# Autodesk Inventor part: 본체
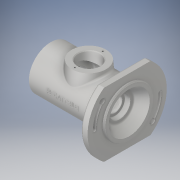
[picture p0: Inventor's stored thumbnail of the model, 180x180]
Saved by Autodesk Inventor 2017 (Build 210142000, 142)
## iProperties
Part Number: 본체
Material: 알루미늄 6061
Document SubType Name: Modeling
Designer: Administrator
Density: 2.7 g/cm^3
Appearance: 알루미늄 - 평지
Mass: 687.877 g
Surface Area: 621.651 cm^2
Volume: 254.769 cm^3
Author: Administrator
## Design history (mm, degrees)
sketch "스케치1"
  geometry: L1 (0, 0)-(102, 0); L2 (0, 0)-(0, 32); L3 (0, 32)-(102, 32); L4 (102, 32)-(102, 0)
  constraints: 8 end point, 2 horizontal, 1 perpendicular, 1 vertical
  dimensions: "d0" = 102 distance of L1.start L1.end; "d1" = 64 diameter of L3 L1
revolve "회전1" sketch "스케치1" stored, may be unused: angle "d2" = 90 deg
sketch "스케치2"
  geometry: L1 (-33.985, 47)-(33.985, 47); L2 (-33.985, -47)-(33.985, -47); A1 r 58 centre (0, 0) between (-33.985, 47) and (-33.985, -47); A2 r 58 centre (0, 0) between (33.985, 47) and (-33.985, 47); A3 r 58 centre (0, 0) between (33.985, -47) and (33.985, 47); A4 r 58 centre (0, 0) between (-33.985, -47) and (33.985, -47); 1 further point
  constraints: 9 point on circle, 4 centre point, 4 end point, 2 horizontal, 1 coincident
  dimensions: "d3" = 116 diameter of A1; "d4" = 94 distance between parallel lines of L2 L1; "d5" = 47 distance from line of point (0, 0) L1
extrude "돌출1" join sketch "스케치2" distance "d6" = 10; taper "d7" = 0 deg
sketch "스케치3"
  geometry: C1 r 36 at (0, 0); 1 further point
  constraints: 1 centre point, 1 coincident
  dimensions: "d8" = 72 diameter of C1
extrude "돌출2" join sketch "스케치3" distance "d9" = 3; taper "d10" = 0 deg
sketch "스케치4"
  geometry: L1 (115, 0)-(8, 0); L2 (8, 0)-(8, 24); L3 (0, -32)-(0, 32) reference; L4 (8, 24)-(11, 24); L5 (11, 24)-(11, 22.5); L6 (11, 22.5)-(22, 22.5); L7 (22, 22.5)-(22, 17.5); L8 (22, 17.5)-(24.25, 17.5); L9 (24.25, 17.5)-(24.25, 18.5); L10 (24.25, 18.5)-(26, 18.5); L11 (26, 18.5)-(26, 17.5); L12 (26, 17.5)-(37, 17.5); L13 (37, 17.5)-(37, 27); L14 (37, 27)-(75, 27); L15 (75, 27)-(75, 17.5); L16 (75, 17.5)-(85.4, 17.5); L17 (86, 16.9)-(86, 15); L18 (86, 15)-(91, 15); L19 (91, 15)-(91, 11); L20 (91, 11)-(93.7, 11); L21 (93.7, 11)-(93.7, 14.5); L22 (101, 15.404)-(101, 20); L23 (101, 20)-(115, 30); L24 (115, -36)-(115, 36) reference; L25 (94.2, 15)-(100.3, 15); L26 (100.3, 15)-(101, 15.404); L27 (115, 30)-(115, 0); A1 r 0.5 centre (94.2, 14.5) between (94.2, 15) and (93.7, 14.5); A2 r 0.6 centre (85.4, 16.9) between (86, 16.9) and (85.4, 17.5); 4 further points
  constraints: 50 end point, 10 perpendicular, 6 horizontal, 5 point on line, 4 point on circle, 4 tangent, 4 vertical, 3 midpoint, 2 centre point, 2 collinear, 2 horizontal alignment
  dimensions: "d11" = 8 distance between parallel lines of L3 L2; "d12" = 48 diameter of L4 L1; "d13" = 3 distance of L2.end L4.end; "d14" = 45 diameter of L6 L1; "d15" = 37 diameter of L10 L1; "d16" = 4 distance between parallel lines of L11 L7; "d17" = 1.75 distance of L9.end L10.end; "d19" = 35 diameter of L12 L1; "d20" = 22 distance between parallel lines of L3 L7; "d21" = 11 horizontal distance of L13.end L10.end; "d22" = 38 distance of L13.end L14.end; "d23" = 54 diameter of L14 L1; "d24" = 30 diameter of L18 L1; "d25" = 22 diameter of L20 L1; "d27" = 40 diameter of L22.end L1; "d28" = 11 distance of L15.end point (86, 17.5); "d29" = 5 distance of L17.end L18.end; "d30" = 14 distance between parallel lines of L22 L24; "d31" = 7.3 distance between parallel lines of L22 L21; "d32" = 30 diameter of L25 L1; "d33" = 0.7 distance from line of L22 L25.end; "d34" = 30 deg angle of L25 L26; "d35" = 0.5 radius of A1 (derived); "d36" = 0.6 radius of A2; "d37" = 60 diameter of L23.end L1
revolve "회전2" sketch "스케치4" stored, may be unused: angle "d38" = 90 deg
node "작업 평면1"
sketch "스케치5"
  geometry: L1 (0, 32)-(0, -32) reference; C1 r 25 at (-56, 0); 1 further point
  constraints: 1 centre point, 1 horizontal alignment
  dimensions: "d40" = 50 diameter of C1; "d41" = 56 distance from line of L1 C1.centre
extrude "돌출3" join sketch "스케치5" stored distance "d42" = 3; taper "d43" = 5 deg
sketch "스케치6"
  geometry: C1 r 25 at (0, 0) reference; C2 r 16 at (0, 0); 1 further point
  constraints: 1 centre point, 1 coincident
  dimensions: "d44" = 32 diameter of C2
extrude "돌출4" cut sketch "스케치6" distance "d45" = 30; taper "d46" = 0 deg
sketch "스케치7"
  geometry: 2 further points
  constraints: 1 coincident
hole "구멍1" sketch "스케치7" at (0, 0) diameter "d47" = 43.376; stored, may be unused: countersink angle "d51" = 90 deg, drill point angle "d53" = 118 deg; dims "d48" = 9, "d49" = 4, "d50" = 2, "d52" = 9
sketch "스케치8"
  geometry: C1 r 16 at (0, 0) reference; A1 r 20.5 centre (0, 0) between (0, 20.5) and (0, -20.5); 1 further point
  constraints: 2 point on circle, 2 vertical alignment, 1 centre point, 1 coincident
  dimensions: "d54" = 41 diameter of A1
hole "구멍2" sketch "스케치8" at (0, 20.5), (0, -20.5) diameter "d55" = 2.459; stored, may be unused: countersink angle "d59" = 90 deg, drill point angle "d61" = 118 deg; dims "d56" = 6, "d57" = 4, "d58" = 2, "d60" = 8
sketch "스케치9" dims "d62" = 96
  geometry: L1 (0, 0)-(-36.77, -30.854); L2 (0, 0)-(-48, 0); A1 r 48 centre (0, 0) between (-48, 0) and (-36.77, -30.854); A2 r 52 centre (0, 0) between (-52, 0) and (-39.834, -33.425); A3 r 44 centre (0, 0) between (-44, 0) and (-33.706, -28.283); A4 r 4 centre (-48, 0) between (-44, 0) and (-52, 0); A5 r 4 centre (-36.77, -30.854) between (-39.834, -33.425) and (-33.706, -28.283); 2 further points
  constraints: 10 point on circle, 5 centre point, 4 end point, 4 tangent, 2 coincident, 1 horizontal, 1 horizontal alignment, 2 other
  dimensions: "d63" = 40 deg angle of L2 L1; "d64" = 8 diameter of A5
extrude "돌출5" cut sketch "스케치9" distance "d65" = 4.4; taper "d66" = 0 deg
sketch "스케치10" dims "d67" = 96
  geometry: L1 (0, 0)-(-36.77, -30.854); L2 (0, 0)-(-48, 0); A1 r 48 centre (0, 0) between (-48, 0) and (-36.77, -30.854); A2 r 50.25 centre (0, 0) between (-50.25, 0) and (-38.494, -32.3); A3 r 45.75 centre (0, 0) between (-45.75, 0) and (-35.047, -29.408); A4 r 2.25 centre (-48, 0) between (-45.75, 0) and (-50.25, 0); A5 r 2.25 centre (-36.77, -30.854) between (-38.494, -32.3) and (-35.047, -29.408); 2 further points
  constraints: 10 point on circle, 5 centre point, 4 end point, 4 tangent, 2 coincident, 1 horizontal, 1 horizontal alignment, 2 other
  dimensions: "d68" = 40 deg angle of L2 L1; "d69" = 4.5 diameter of A5
extrude "돌출6" cut sketch "스케치10" distance "d70" = 10; taper "d71" = 0 deg
sketch "스케치11"
  geometry: C1 r 4 at (-36.77, -30.854); A1 r 4 centre (-36.77, -30.854) between (-39.834, -33.425) and (-33.706, -28.283) reference; 1 further point
  constraints: 1 centre point, 1 coincident
  dimensions: "d72" = 8 diameter of C1
extrude "돌출7" cut sketch "스케치11" distance "d73" = 15; taper "d74" = 0 deg
node "작업 평면2"
sketch "스케치12"
  geometry: L1 (112, -47)-(112, 47) reference; 2 further points
  constraints: 1 horizontal alignment, 1 other
  dimensions: "d79" = 62 distance from line of L1 point (50, 0)
feature "엠보싱1" sketch "스케치12" dims "d80" = 0.5, "d81" = 0
fillet "모깎기1" dims "d82" = 3
fillet "모깎기2" dims "d83" = 3
fillet "모깎기3" dims "d84" = 3
chamfer "모따기1" distance "d85" = 1; stored, may be unused: second distance "d86" = 2, angle "d87" = 45 deg
chamfer "모따기2" distance "d88" = 1; stored, may be unused: second distance "d89" = 2, angle "d90" = 45 deg
node "솔리드1"
pattern_circular "원형 패턴1" dims angle "d76" = 360 deg
other parameters: "d39" = 38
